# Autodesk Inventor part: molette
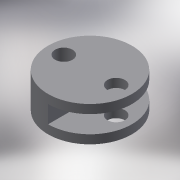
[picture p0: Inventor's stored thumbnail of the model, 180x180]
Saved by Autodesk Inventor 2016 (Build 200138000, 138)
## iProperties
Shininess: 64.0
Length Units: 11269
Angle Units: 11279
Time Units: 11290
Mass Units: 11283
Length Display Precision: 3
Angle Display Precision: 2
Compacted: True
Part Number: molette
Document SubType Name: Modeling
Created: 2003-07
Material: Générique
Designer: trameau
Density: 1 g/cm^3
Appearance: Par défaut
Density: 0.0
Volumn: 0.0
Area: 0.0
PropertySet Name: Model Information
Control State: 0
Master: False
Checked Out: False
Author: trameau
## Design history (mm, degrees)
sketch "Esquisse1"
  geometry: C1 r 24 at (0, 0)
  constraints: 1 centre point
  dimensions: "d0" = 48 diameter of C1
extrude "Extrusion1" new body sketch "Esquisse1" distance "d1" = 5; taper "d2" = 0 deg
sketch "Esquisse2"
  geometry: C1 r 24 at (0, 0) reference; 1 further point
  dimensions: "d3" = 15 distance of point (15, 0) C1.centre
hole "Perçage1" sketch "Esquisse2" at (15, 0) diameter "d4" = 10; stored, may be unused: countersink angle "d8" = 82 deg, drill point angle "d10" = 118 deg; dims "d5" = 6, "d6" = 4, "d7" = 2, "d9" = 8
pattern_circular "Réseau circulaire1" dims angle "d13" = 360 deg
sketch "Esquisse3"
  geometry: L1 (0, 24)-(0, -24); C1 r 5 at (-15, 0) reference; A1 r 24 centre (0, 0) between (0, 24) and (0, -24) reference
  constraints: 2 end point, 2 point on circle, 1 vertical
extrude "Extrusion2" join sketch "Esquisse3" distance "d14" = 5; taper "d15" = 0 deg
mirror "Symétrie1"
node "Solide1"
node "Corps solides"
node "Corps surfaciques"
